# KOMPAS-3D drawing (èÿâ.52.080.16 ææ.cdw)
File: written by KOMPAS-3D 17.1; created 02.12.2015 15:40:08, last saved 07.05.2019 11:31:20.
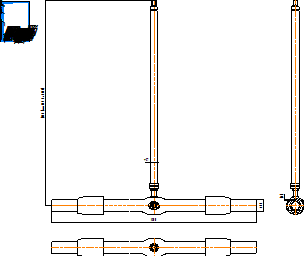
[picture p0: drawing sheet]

Sheet 1: A4, portrait

Title block, sheet 1: name: КШГ.52.080.16 СС; material: Внимание! Данный продукт является объектом авторского права ООО «Торговый Дом АДЛ». / Запрещается изменение, копирование, распространение / (в том числе путем копирования на другие сайты и ресурсы в Интернете) / или любое иное использование информации и объектов без предварительного / согласия правообладателя (ООО «Торговый Дом АДЛ»).; sheets: 1; organisation: ООО "Торговый дом АДЛ"; sheet format: A4; stored path: C:\Users\kka\KOMPAS_Work\Модели кранов для исследований\DN50\С удлинением\КШГ.32.050.40 СС ГЧ _ Шаровой кран БИВАЛ Ду50 Ру4 МПа редуцированный под приварку, с удлинением штока H=1100.cdw; drawn by: Климкович К.А.; drawn by, date: 02.12.15

Views: Вид 1, Проекционный вид 2
Referenced files in C:\Users\kka\KOMPAS_Work\Модели кранов для исследований\DN80\С удлинением\: КШТ.22.080.25 СС.a3d, КШГ.35.065.25 СС.a3d!КШГ.45.065.10 СС!Деталь (локальная).m3d
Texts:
  Klimkovich
  ADL
  (от 297 до 5000)
Dimensions and other numbers on the sheet: 1500; 57; 90; 10,1; 1:1; 1; 02.12.15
